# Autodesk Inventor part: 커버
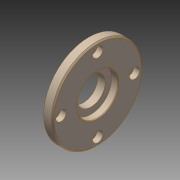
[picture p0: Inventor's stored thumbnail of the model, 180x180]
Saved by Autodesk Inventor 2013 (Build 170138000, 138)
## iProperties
Created: 2024-02
Part Number: 커버
Material: 알루미늄 6061
Document SubType Name: Modeling
Designer: mdu-01
Density: 1 g/cm^3
Author: mdu-01
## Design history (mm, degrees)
sketch "스케치1"
  geometry: L1 (0, 0)-(12, 0); L2 (0, 20.5)-(0, 22.5); L3 (1, 23.5)-(5, 23.5); L4 (5, 23.5)-(5, 35); L5 (5, 35)-(11, 35); L6 (12, 34)-(12, 16.289); L7 (11.5, 16)-(6.8, 16); L8 (6.8, 16)-(6.8, 11); L9 (6.8, 11)-(1, 11); L10 (1, 11)-(1, 20.5); L11 (1, 20.5)-(0, 20.5); L12 (11.5, 16)-(12, 16.289); L13 (0, 22.5)-(1, 23.5); L14 (11, 35)-(12, 34); 3 further points
  constraints: 28 end point, 8 parallel, 8 point on line, 2 perpendicular, 1 horizontal
  dimensions: "d0" = 12 distance of L1.start L1.end; "d1" = 70 diameter of L5 L1; "d2" = 5 distance between parallel lines of L4 L2; "d3" = 47 diameter of L3 L1; "d4" = 41 diameter of L11 L1; "d5" = 22 diameter of L9 L1; "d6" = 32 diameter of L7 L1; "d7" = 1 distance between parallel lines of L2 L10; "d8" = 5.2 distance between parallel lines of L6 L8; "d10" = 0.5 distance of L7.start point (12, 16); "d11" = 30 deg angle of L7 L12; "d12" = 1 distance of L2.end point (0, 23.5); "d13" = 1 distance of L3.start point (0, 23.5) (= d12); "d14" = 1 distance of L5.end point (12, 35); "d15" = 1 distance of L6.start point (12, 35) (= d14)
revolve "회전1" sketch "스케치1" stored, may be unused: angle "d16" = 90 deg
sketch "스케치2" dims "d17" = 57
  geometry: 3 further points
  constraints: 2 vertical alignment, 1 coincident, 2 other
hole "구멍1" sketch "스케치2" at (0, 28.5) diameter "d18" = 4.5; stored, may be unused: countersink angle "d22" = 90 deg, drill point angle "d24" = 118 deg; dims "d19" = 6, "d20" = 8, "d21" = 4.4, "d23" = 8
node "솔리드1"
pattern_circular "원형 패턴1" dims angle "d26" = 360 deg
